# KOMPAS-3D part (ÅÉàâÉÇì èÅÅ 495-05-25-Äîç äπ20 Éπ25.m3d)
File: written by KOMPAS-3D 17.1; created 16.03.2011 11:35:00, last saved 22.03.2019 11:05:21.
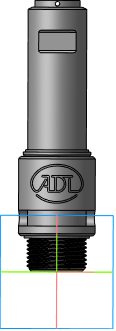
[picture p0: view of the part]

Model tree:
1. Плоскость XY
2. Плоскость ZX
3. Плоскость ZY
4. Ось X
5. Ось Y
6. Ось Z
7. Начало координат
8. Операция без истории:2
